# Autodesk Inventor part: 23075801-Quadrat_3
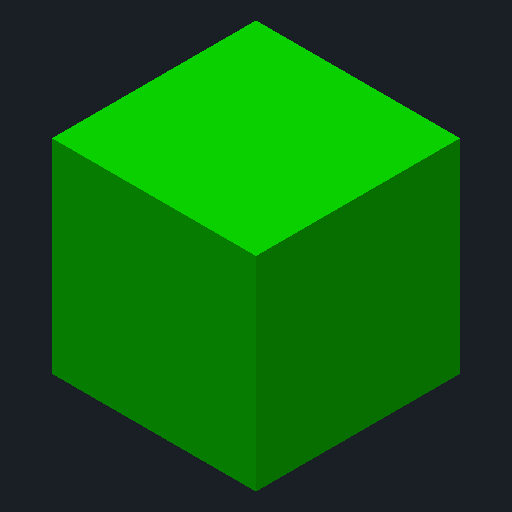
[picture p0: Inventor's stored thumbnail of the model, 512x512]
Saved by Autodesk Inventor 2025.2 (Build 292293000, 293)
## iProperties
Company: Ed. Züblin AG
Created: 2025-03
Part Number: 23075801-Quadrat_3
Material: Stahlbeton C30/37
Document SubType Name: Modeling
Designer: FrodlSte
Mass: 2.5e+06 g
Surface Area: 60000 cm^2
Volume: 1e+06 cm^3
Density: 2.5 g/cm^3
Appearance: Beton C30/37
Description: Ausbruch
z_Bereich: Tunnelbau
z_Direktion: Tief- und Tunnelbau
z_Konzerneinheit: Zentrale Technik
z_Matchkey: =<z_Matchkey_010>_<z_Matchkey_020>_<z_Matchkey_030>_<z_Matchkey_040>_<z_Matchkey_050>_<z_Matchkey_060>_<z_Matchkey_070>_<z_Matchkey_080>_<z_Matchkey_090>_<z_Mat
cpiComponentType: Attribut
cpiFitMatchkey: =<z_Matchkey>
z_Matchkey_010: xxxxx
z_Matchkey_020: 5DTUB
z_Matchkey_030: xxx
z_Matchkey_040: xxx
z_Matchkey_050: xxx
z_Matchkey_060: xxx
z_Matchkey_070: xxx
z_Matchkey_080: xxx
z_Matchkey_090: xxx
z_Matchkey_100: xxx
z_Matchkey_110: xxx
z_Matchkey_120: xxxxxxx
z_Matchkey_130: STRO
z_Matchkey_140: xxxx
DocNumber: 23075801-Quadrat_3.ipt
Folder: DL23075801-DE-Pfaffensteigtunnel\BIM\Testmodell
VDS_Category: 09 - BIM - Konstruktion
DBSet_Element:010_Eigentuemer: DBE
DBSet_Element:020_Autor: ND
DBSet_Element:030_Projektnummer: G.016268527
DBSet_Element:040_Bereich: ND
DBSet_Element:050_Vertragspartner: ND
DBSet_Element:060_Gewerk: ND
DBSet_Element:070_Bauwerk: EW
DBSet_Element:080_Bauwerksnummer: 17030
DBSet_Element:090_Bezeichnung: ND
DBSet_Element:100_Gruppe: Ausbruch
DBSet_Element:110_Element: Ausbruch
DBSet_Element:120_Elementtyp: Kalotte
DBSet_Element:130_Identifikationsnummer: ND
DBSet_Element:140_Position_1: KALO
DBSet_Element:150_Position_2: FIRS
DBSet_Element:160_PUID: ND
DBSet_Element:170_Hauptmaterialitaet: ND
DBSet_Element:171_Materialindikator_1: ND
DBSet_Element:172_Materialindikator_2: ND
DBSet_Geometrie:Flaeche: -99999.0
DBSet_Geometrie:Laenge: -99999.0
DBSet_Geometrie:Volumen_Solid: 7.21
DBSet_Position:Streckenachse: ND
DBSet_Position:Streckenkilometer_Anfang: -99999
DBSet_Position:Streckenkilometer_Ende: -99999
DBSet_Position:Tunnelachse: ND
DBSet_Position:Tunnelmeter_Anfang: -99999
DBSet_Position:Tunnelmeter_Ende: -99999
DBSet_TP:Status: ABB
DBSet_TU_Ausbruch:Abrasivitaetsindex: 0.4
DBSet_TU_Ausbruch:Abrechnungsquerschnitt: -99999.0
DBSet_TU_Ausbruch:Abschlagslaenge: -99999.0
DBSet_TU_Ausbruch:Ausfuehrungsrichtung: fallend
DBSet_TU_Ausbruch:Grenzwassermenge: bis_0,5l/s
DBSet_TU_Ausbruch:Homogenbereich: 1
DBSet_TU_Ausbruch:Modus: ND
DBSet_TU_Ausbruch:Stuetzmittel: Druckluft
DBSet_TU_Ausbruch:ta_cm: 30
DBSet_TU_Ausbruch:tb_cm: 100
DBSet_TU_Ausbruch:td_cm: 300
DBSet_TU_Ausbruch:ti_cm: 300
DBSet_TU_Ausbruch:ue_cm: 400
DBSet_TU_Ausbruch:Vortriebsabschnitt: N-1.1
DBSet_TU_Ausbruch:Vortriebsklasse: ND
DBSet_TU_Ausbruch:Wasserzufluss: 0-3
z_DBSet_Element:010_Eigentuemer: DBInfraGo
z_DBSet_Element:020_Autor: Vertragspartner 2 ZB
z_DBSet_Element:030_Projektnummer: Gaeubahn Nord HP Goldberg (DBnfraGO, BK11)
z_DBSet_Element:040_Bereich: PFA 1 Tunnel
z_DBSet_Element:050_Vertragspartner: Tunnel
z_DBSet_Element:060_Gewerk: Tunnelbau
z_DBSet_Element:070_Bauwerk: SBW-Tu
z_DBSet_Element:080_Bauwerksnummer: zzz (leer)
z_DBSet_Element:090_Bezeichnung: zzz (leer)
z_DBSet_Element:100_Gruppe: Ausbruch
z_DBSet_Element:110_Element: Ausbruch
z_DBSet_Element:120_Elementtyp: Strosse
z_DBSet_Element:130_Identifikationsnummer: nicht definiert
z_DBSet_Element:140_Position_1: Strosse
z_DBSet_Element:150_Position_2: Nicht definiert
z_DBSet_Element:160_PUID: nicht definiert
z_DBSet_Element:170_Hauptmaterialitaet: nicht definiert
z_DBSet_Element:171_Materialindikator_1: nicht definiert
z_DBSet_Element:172_Materialindikator_2: nicht definiert
z_DBSet_Geometrie:Flaeche: 1,000 m^2
z_DBSet_Geometrie:Laenge: -99999,000 m
z_DBSet_Position:Streckenachse: zzz (leer)
z_DBSet_Position:Streckenkilometer_Anfang: -11111,000 oE
z_DBSet_Position:Streckenkilometer_Ende: -11111,000 oE
z_DBSet_Position:Tunnelachse: zzz (leer)
z_DBSet_Position:Tunnelmeter_Anfang: -11111,000 oE
z_DBSet_Position:Tunnelmeter_Ende: -11111,000 oE
z_DBSet_TP:Status: Neubau
z_DBSet_TU_Ausbruch:Abrasivitaetsindex: zzz (leer)
z_DBSet_TU_Ausbruch:Abrechnungsquerschnitt: -99999,000 m^2
z_DBSet_TU_Ausbruch:Abschlagslaenge: 2,000 m
z_DBSet_TU_Ausbruch:Ausfuehrungsrichtung: zzz (leer)
z_DBSet_TU_Ausbruch:Grenzwassermenge: zzz (leer)
z_DBSet_TU_Ausbruch:Homogenbereich: zzz (leer)
z_DBSet_TU_Ausbruch:Modus: Abbaukammer vollstaendig gefuellt
z_DBSet_TU_Ausbruch:Stuetzmittel: Nicht definiert
z_DBSet_TU_Ausbruch:Vortriebsabschnitt: zzz (leer)
z_DBSet_TU_Ausbruch:Vortriebsklasse: zzz (leer)
z_DBSet_TU_Ausbruch:Wasserzufluss: zzz (leer)
z_DBSet_Geometrie:Volumen_Solid: -11111,000 m^3
z_DBSet_TU_Ausbruch:ta_cm: 30,000 cm
z_DBSet_TU_Ausbruch:tb_cm: 100,000 cm
z_DBSet_TU_Ausbruch:td_cm: 300,000 cm
z_DBSet_TU_Ausbruch:ti_cm: 300,000 cm
z_DBSet_TU_Ausbruch:ue_cm: 400,000 cm
Author: FrodlSte
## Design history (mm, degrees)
derived "23075801-Skelett.ipt"
node "Quadrat_3"
node "Volumenkörpern"
node "Oberflächenkörpern"
feature "Quadrat_3::23075801-Skelett.ipt" dims "d4" = 10
tag "Bezeichnung1"
other parameters: "Ausbruchsfläche_Strosse_Area" = 100000 [user parameter; used in 2 equation terms], "test" = 100000 (= Ausbruchsfläche_Strosse_Area) [user parameter]
